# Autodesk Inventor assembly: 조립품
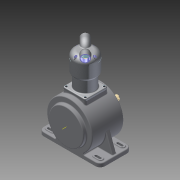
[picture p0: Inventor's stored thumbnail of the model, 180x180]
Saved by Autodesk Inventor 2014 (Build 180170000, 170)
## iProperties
Created: 2015-06
Part Number: 조립품
Document SubType Name: Assembly
Designer: 시험용
Author: 시험용
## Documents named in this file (15)
- C:\Users\시험용\Desktop\인벤터\조립품.iam
- C:\Users\시험용\Desktop\인벤터\본체.ipt
- C:\Users\시험용\Desktop\인벤터\M4x0.7.ipt
- C:\Users\시험용\Desktop\인벤터\M5x0.8.ipt
- C:\Users\시험용\Desktop\인벤터\메인 크랭크 축-구동부.ipt
- C:\Users\시험용\Desktop\인벤터\메인커버.ipt
- C:\Users\시험용\Desktop\인벤터\베어링 6204.ipt
- C:\Users\시험용\Desktop\인벤터\베어링 NA 4902.ipt
- C:\Users\시험용\Desktop\인벤터\실린더.ipt
- C:\Users\시험용\Desktop\인벤터\실린더헤드.ipt
- C:\Users\시험용\Desktop\인벤터\오일실.ipt
- C:\Users\시험용\Desktop\인벤터\커넥팅 로드.ipt
- C:\Users\시험용\Desktop\인벤터\크랭크 서브축.ipt
- C:\Users\시험용\Desktop\인벤터\피스톤 핀.ipt
- C:\Users\시험용\Desktop\인벤터\피스톤.ipt
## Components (14 placed, 4 different names)
1. 피스톤:1
2. 피스톤 핀:1
3. M4x0.7:1
4. M4x0.7:2
5. M4x0.7:3
6. M4x0.7:4
7. M5x0.8:1
8. M5x0.8:2
9. M5x0.8:3
10. M5x0.8:4
11. M4x0.7:5
12. M4x0.7:6
13. M4x0.7:7
14. M4x0.7:8
